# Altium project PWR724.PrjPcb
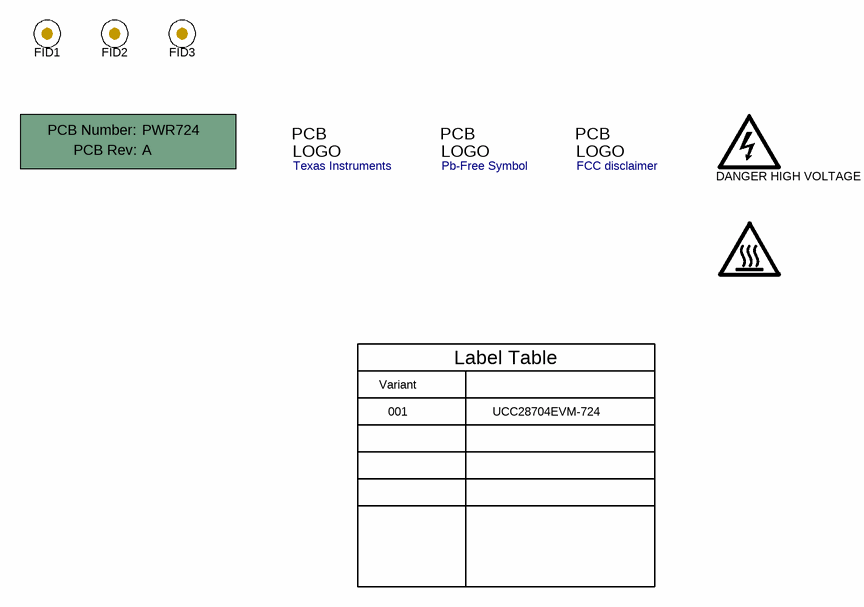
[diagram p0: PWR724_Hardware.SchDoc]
CopyrightYear: 2015; PCB_Layout: M O'Loughlin; PCB_Rev: A; PRJ_Customer: Public Release; PRJ_Engineer: M O'Loughlin; PRJ_Number: PWR724; PRJ_Title: UCC28704EVM-724; SCH_Rev: A; TechSupport: http://www.ti.com/support; TID: N/A
2 sheets, 56 parts. Net scope: global (net labels, ports and power ports of the same name join across sheets).
Board file: PWR724.PcbDoc
Sheets:
  PWR724_Hardware.SchDoc
  PWR724.SchDoc

## Sheet PWR724_Hardware.SchDoc
size 431 x 279 mm; Date: Not shown in title block; ApprovedBy: Not shown in title block; CheckedBy: Not shown in title block; Author: Not shown in title block; CompanyName: Not shown in title block; Engineer: Not shown in title block; Organization: Not shown in title block; Address1: Not shown in title block; Address2: Not shown in title block; Address3: Not shown in title block; Address4: Not shown in title block; DocumentNumber: 1; Revision: Use project parameter SCH_Rev; SheetNumber: 3; SheetTotal: 3; PageSetup: Record=PageOptions¦CenterHorizontal=True¦CenterVertical=True¦PrintScale=1.00¦XCorrection=1.00¦YCorrection=1.00¦PrintKind=0¦BorderSize=5000000¦LeftOffset=0¦BottomOffset=0¦Orientation=2¦PaperLength=1000¦PaperWidth=1000¦Scale=100¦PaperSource=15¦PrintQuality=600¦MediaType=1¦DitherType=10¦PaperKind=Letter¦PrintScaleMode=1

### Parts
!PCB  Printed Circuit Board  (value not drawn)  (mechanical)
FID1  Fiducial  [Fiducial10-20]  (value not drawn)
FID2  Fiducial  [Fiducial10-20]  (value not drawn)
FID3  Fiducial  [Fiducial10-20]  (value not drawn)
Logo1  Texas Instruments  [TI_Stacked_Overlay_Small]  (no BOM)
Logo2  Pb-Free Symbol  [Pb-Free_Overlay_Small]  (no BOM)
Logo3  FCC disclaimer  [FCC_disclaimer]  (no BOM)
LOGO4  DANGER HIGH VOLTAGE  [IEC_HighVoltage_Small]  (no BOM)
LOGO5  CAUTION HOT SURFACE  [IEC_HotSurface_Small]  (value not drawn)  (no BOM)

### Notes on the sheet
- Variant
- Label Table
- 001
- UCC28704EVM-724

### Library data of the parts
!PCB = PCB: Manufacturer: Any; PartNumber: PWR724; SymbolCreator: a0412235
FID1-FID3 = Fiducial: Fiducial mark.  There is nothing to buy or mount.; SymbolCreator: codlsc
Logo1 = TI_Logo: Texas Instrument Corporate Signature; SymbolCreator: a0412235
Logo2 = Pb-Free: SymbolCreator: a0412235
Logo3 = FCC_disclaimer: SymbolCreator: codlsc
LOGO4 = IEC_HighVoltage: IEC 61010-1 High Voltage Warning; SymbolCreator: a0412235
LOGO5 = IEC_HotSurface: IEC 61010-1 Hot Surface Warning; SymbolCreator: a0412235

## Sheet PWR724.SchDoc
size 431 x 279 mm; Date: Not shown in title block; ApprovedBy: Not shown in title block; CheckedBy: Not shown in title block; Author: Not shown in title block; CompanyName: Not shown in title block; Engineer: Not shown in title block; Organization: Not shown in title block; Address1: Not shown in title block; Address2: Not shown in title block; Address3: Not shown in title block; Address4: Not shown in title block; DocumentNumber: 1; Revision: Use project parameter SCH_Rev; SheetNumber: 1; SheetTotal: 3; PageSetup: Record=PageOptions¦CenterHorizontal=True¦CenterVertical=True¦PrintScale=1.00¦XCorrection=1.00¦YCorrection=1.00¦PrintKind=0¦BorderSize=5000000¦LeftOffset=0¦BottomOffset=0¦Orientation=2¦PaperLength=1000¦PaperWidth=1000¦Scale=100¦PaperSource=15¦PrintQuality=600¦MediaType=1¦DitherType=10¦PaperKind=Letter¦PrintScaleMode=1
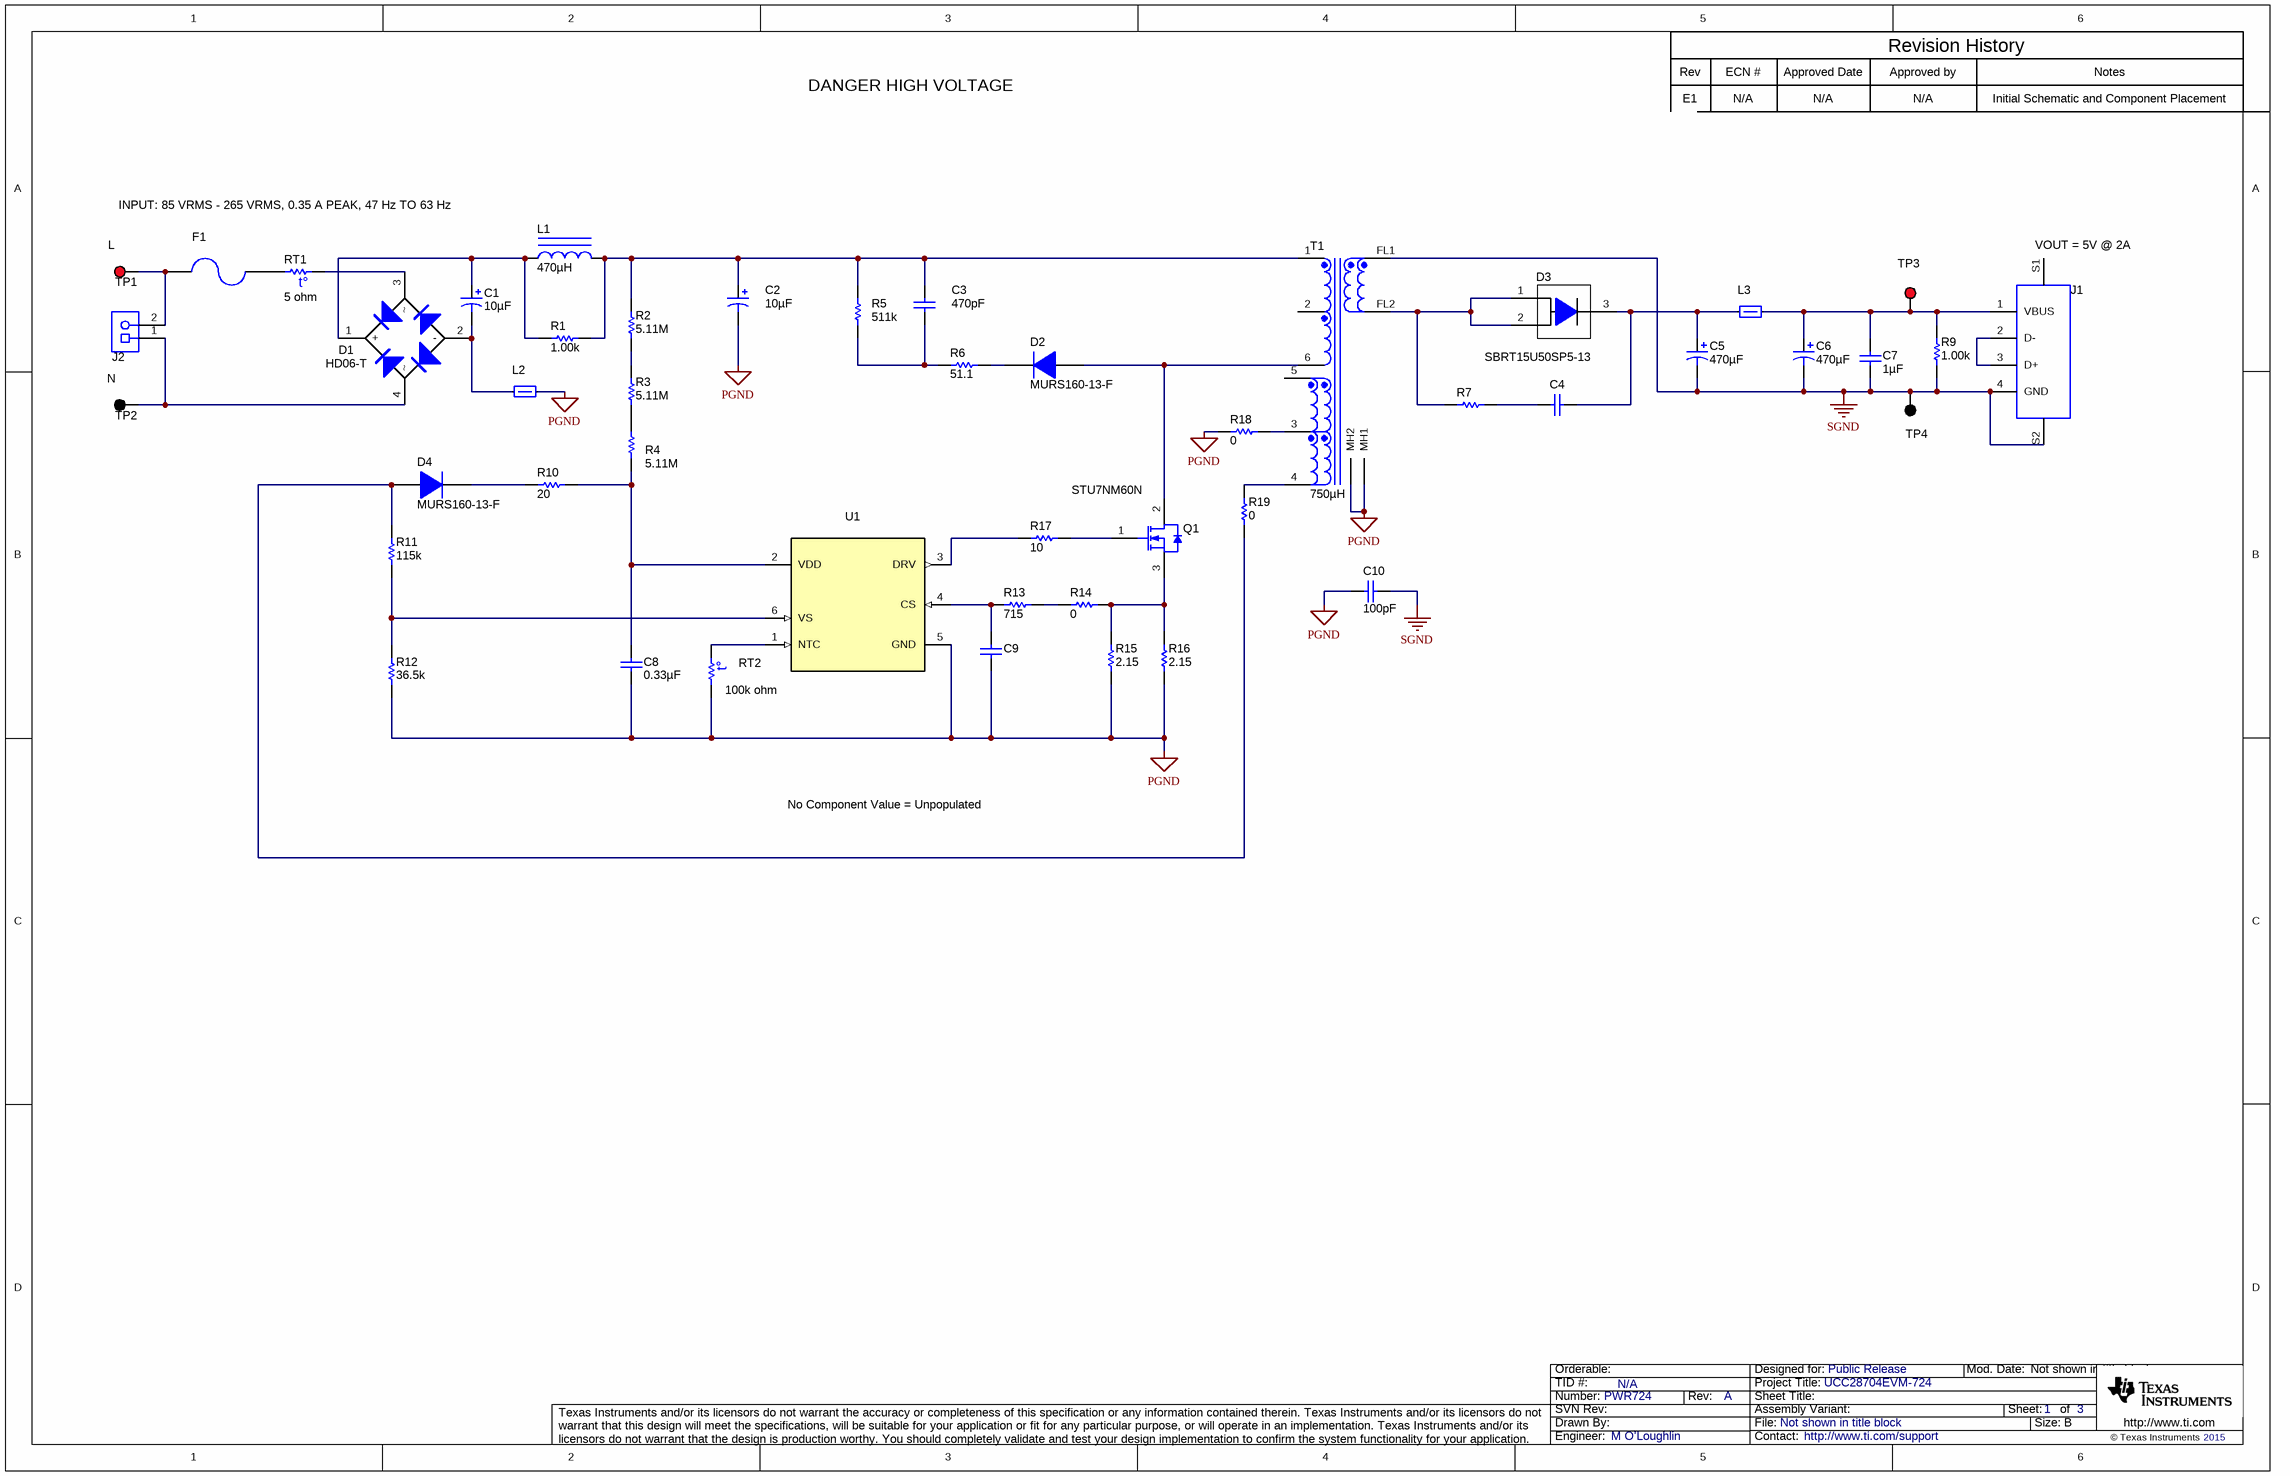
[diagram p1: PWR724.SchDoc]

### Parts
C1  ValueDisplayed: 10µF  [CAPPRD500W60D1000H2000_Horizontal_DOWN]  (hidden comment: UCS2G100MPD1TD)
C2  ValueDisplayed: 10µF  [CAPPRD500W60D1000H2000_Horizontal_UP]  (hidden comment: UCS2G100MPD1TD)
C3  ValueDisplayed: 470pF  [1206]  (hidden comment: GRM31A7U2J471JW31D)
C4  08055A101JAT2A  [0805_HV]  (value not drawn)
C5  ValueDisplayed: 470µF  [LF_1000x1300]  (hidden comment: PLF1C471MDO1)
C6  ValueDisplayed: 470µF  [LF_1000x1300]  (hidden comment: PLF1C471MDO1)
C7  ValueDisplayed: 1µF  [0603]  (hidden comment: C1608X7R1E105K080AB)
C8  ValueDisplayed: 0.33µF  [1206]  (hidden comment: GRM319R71H334KA01D)
C9  06035A270JAT2A  [0603]  (value not drawn)
C10  ValueDisplayed: 100pF  [CD_700x1100x700]  (hidden comment: CD70-B2GA101KYNKA)
D1  HD06-T  [MiniDIP]
D2  MURS160-13-F  [SMB]
D3  SBRT15U50SP5-13  [PowerDI5]
D4  MURS160-13-F  [SMB]
F1  RST 500  [Fuse_RST]  (value not drawn)
J1  923  [Keystone_923]  (value not drawn)
J2  1715721  [PhoenixContact_1715721]  (value not drawn)
L1  ValueDisplayed: 470µH  [RLB0914]  (hidden comment: RLB0914-471KL)
L2  742792121  [1206_190]  (value not drawn)
L3  742792121  [1206_190]  (value not drawn)
Q1  STU7NM60N  [IPAK]
R1  ValueDisplayed: 1.00k  [1206]  (hidden comment: CRCW12061K00FKEA)
R2  ValueDisplayed: 5.11M  [0805_HV]  (hidden comment: CRCW08055M11FKEA)
R3  ValueDisplayed: 5.11M  [0805_HV]  (hidden comment: CRCW08055M11FKEA)
R4  ValueDisplayed: 5.11M  [0805_HV]  (hidden comment: CRCW08055M11FKEA)
R5  ValueDisplayed: 511k  [1206]  (hidden comment: CRCW1206511KFKEA)
R6  ValueDisplayed: 51.1  [0805_HV]  (hidden comment: CRCW080551R1FKEA)
R7  CRCW0805510KJNEA  [0805_HV]  (value not drawn)
R9  ValueDisplayed: 1.00k  [0603]  (hidden comment: CRCW06031K00FKEA)
R10  ValueDisplayed: 20  [0805_HV]  (hidden comment: CRCW080520R0JNEA)
R11  ValueDisplayed: 115k  [0805_HV]  (hidden comment: CRCW0805115KFKEA)
R12  ValueDisplayed: 36.5k  [0603]  (hidden comment: CRCW060336K5FKEA)
R13  ValueDisplayed: 715  [0603]  (hidden comment: RC0603FR-07715RL)
R14  ValueDisplayed: 0  [1206]  (hidden comment: MCR18EZHJ000)
R15  ValueDisplayed: 2.15  [0805_HV]  (hidden comment: CRCW08052R15FKEA)
R16  ValueDisplayed: 2.15  [0805_HV]  (hidden comment: CRCW08052R15FKEA)
R17  ValueDisplayed: 10  [0603]  (hidden comment: CRCW060310R0JNEAHP)
R18  ValueDisplayed: 0  [1206]  (hidden comment: MCR18EZHJ000)
R19  ValueDisplayed: 0  [1206]  (hidden comment: MCR18EZHJ000)
RT1  value 5 ohm  [MF72D5]  (hidden comment: MF72-005D5)
RT2  value 100k ohm  [0603]  (hidden comment: NTCG164KF104F)
T1  ValueDisplayed: 750µH  [Wurth_750315841]  (hidden comment: 750315841)
TP1  5010  [Keystone5010]  (value not drawn)
TP2  5011  [Keystone5011]  (value not drawn)
TP3  5010  [Keystone5010]  (value not drawn)
TP4  5011  [Keystone5011]  (value not drawn)
U1  UCC28704DBVR-1  [DBV0006A_N]  (value not drawn)

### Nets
PGND: C2.2(-) C8.2 C9.2 C10.2 L2.2 R12.1 R15.1 R16.1 R18.1 RT2.1 T1.MH1 T1.MH2 U1.5(GND)
SGND: C5.2(-) C6.2(-) C7.2 C10.1 J1.4(GND) J1.S2 R9.1 T1.FL1 TP4.1
NetC1_1: C1.1(+) D1.1(+) L1.1 R1.2
NetC1_2: C1.2(-) D1.2(-) L2.1
NetC2_1: C2.1(+) C3.1 L1.2 R1.1 R2.2 R5.2 T1.1
NetC3_2: C3.2 R5.1 R6.1
NetC4_1: C4.1 C5.1(+) D3.3(K) L3.1
NetC4_2: C4.2 R7.2
NetC6_1: C6.1(+) C7.1 J1.1(VBUS) L3.2 R9.2 TP3.1
NetC8_1: C8.1 R4.1 R10.1 U1.2(VDD)
NetC9_1: C9.1 R13.1 U1.4(CS)
NetD1_3: D1.3 RT1.2
NetD1_4: D1.4 J2.1 TP2.1
NetD2_1: D2.1(K) R6.2
NetD2_2: D2.2(A) Q1.2(D) T1.6
NetD3_1: D3.1(A) D3.2(A) R7.1 T1.FL2
NetD4_1: D4.1(K) R10.2
NetD4_2: D4.2(A) R11.2 R19.1
NetF1_1: F1.1 RT1.1
NetF1_2: F1.2 J2.2 TP1.1
NetJ1_2: J1.2(D-) J1.3(D+)
NetQ1_1: Q1.1(G) R17.2
NetQ1_3: Q1.3(S) R14.2 R15.2 R16.2
NetR2_1: R2.1 R3.2
NetR3_1: R3.1 R4.2
NetR11_1: R11.1 R12.2 U1.6(VS)
NetR13_2: R13.2 R14.1
NetR17_1: R17.1 U1.3(DRV)
NetR18_2: R18.2 T1.3
NetR19_2: R19.2 T1.4
NetRT2_2: RT2.2 U1.1(NTC)

Not connected (* = marked no-connect by the designer): J1 S1; T1 2 5

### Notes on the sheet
- DANGER HIGH VOLTAGE
- Rev
- E1
- ECN #
- N/A
- Approved Date
- Approved by
- Revision History
- Notes
- Initial Schematic and Component Placement
- INPUT: 85 VRMS - 265 VRMS, 0.35 A PEAK, 47 Hz TO 63 Hz
- (near TP1) L
- (near J1) VOUT = 5V @ 2A
- (near TP2) N
- No Component Value = Unpopulated

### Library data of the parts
C1 C2 = UCS2G100MPD1TD: CAP, AL, 10 µF, 400 V, +/- 20%, TH; Manufacturer: Nichicon; Polarized: Y; CompType: Capacitor; Value: 10uF; U/M: EA; Cap_F: 0.00001; Tolerance_%: 20; Value1: Unknown; VDC_V: 400; Value2: 400V; IRMS_A: 0.35; TaMin_C: -40; TaMax_C: 105; Cap_Case: CAPPRD500W60D1000H2000; AEC Category: Q200; AEC Qualified: N
C3 = GRM31A7U2J471JW31D: CAP, CERM, 470 pF, 630 V, +/- 5%, U2J, 1206; Manufacturer: MuRata; Polarized: N; CompType: Capacitor; Value: 470pF; U/M: EA; Cap_F: 0.00000000047; Tolerance_%: 5; Value1: Unknown; VDC_V: 630; Value2: 630V; TaMin_C: -55; TaMax_C: 125; AEC Category: Q200
C4 = 08055A101JAT2A: CAP, CERM, 100 pF, 50 V, +/- 5%, C0G/NP0, 0805; Manufacturer: AVX; Polarized: N; CompType: Capacitor; Value: 100pF; U/M: EA; Cap_F: 0.0000000001; Tolerance_%: 5; ESR_ohm: 0.356; Value1: 0.356 ohm; VDC_V: 50; Value2: 50V; TaMin_C: -55; TaMax_C: 125; Cap_Case: 0805; AEC Category: Q200
C5 C6 = PLF1C471MDO1: CAP, AL, 470 µF, 16 V, +/- 20%, 0.009 ohm, TH; Manufacturer: Nichicon; Polarized: Y; CompType: Capacitor; Value: 470uF; U/M: EA; Cap_F: 0.00047; Tolerance_%: 20; VDC_V: 16; Value2: 16V; ESR_ohm: 0.009; IRMS_A: 6.1; TaMin_C: -55; TaMax_C: 105; Cap_Case: 10x13mm; AEC Category: Q200
C7 = C1608X7R1E105K080AB: CAP, CERM, 1 µF, 25 V, +/- 10%, X7R, 0603; Manufacturer: TDK; Polarized: N; CompType: Capacitor; Value: 1uF; U/M: EA; Cap_F: 0.000001; Tolerance_%: 10; Value1: Unknown; VDC_V: 25; Value2: 25V; TaMin_C: -55; TaMax_C: 125; AEC Category: Q200
C8 = GRM319R71H334KA01D: CAP, CERM, 0.33 µF, 50 V, +/- 10%, X7R, 1206; Manufacturer: MuRata; Polarized: N; CompType: Capacitor; Value: 0.33uF; U/M: EA; Cap_F: 0.00000033; Tolerance_%: 10; Value1: Unknown; VDC_V: 50; Value2: 50V; TaMin_C: -55; TaMax_C: 125; AEC Category: Q200
C9 = 06035A270JAT2A: CAP, CERM, 27 pF, 50 V, +/- 5%, C0G/NP0, 0603; Manufacturer: AVX; Polarized: N; CompType: Capacitor; Value: 27pF; U/M: EA; Cap_F: 0.000000000027; Tolerance_%: 5; ESR_ohm: 0.232; Value1: 0.232 ohm; VDC_V: 50; Value2: 50V; TaMin_C: -55; TaMax_C: 125; AEC Category: Q200
C10 = CD70-B2GA101KYNKA: CAP, CERM, 100 pF, 440 V, +/- 10%, B, 7.0x11.0x7.0mm; Manufacturer: TDK; Polarized: N; CompType: Capacitor; Value: 100pF; U/M: EA; VDC_V: 440; Tolerance_%: 10; Cap_F: 0.0000000001; Value1: Unknown; Value2: 440V; TaMin_C: -25; TaMax_C: 105; Cap_Case: 7x7x11mm; AEC Category: Q200
D1 = HD06-T: Diode, Switching-Bridge, 600 V, 0.8 A, MiniDIP; Manufacturer: Diodes Inc.; Value: 600V; U/M: EA; Vf_V: 1; Io_A: 0.8; Value1: 0.8A; Vr_V: 600; Value2: 1V; TJmax_C: 150; AEC Category: Q101
D2 D4 = MURS160-13-F: Diode, Ultrafast, 600 V, 1 A, SMB; Manufacturer: Diodes Inc.; U/M: EA; Vf_V: 1.25; Value: 600V; Value1: 1A; Value2: 1.25V; Io_A: 1; Vr_V: 600; TJmax_C: 150; RJC_CperW: 13; AEC Category: Q101
D3 = SBRT15U50SP5-13: Diode, Super Barrier Rectifier, 50 V, 15 A, AEC-Q101, PowerDI5; Manufacturer: Diodes Inc.; SymbolCreator: a0412235; U/M: EA; Vf_V: 0.47; Value: 50V; Value1: 15A; Value2: 0.47V; Io_A: 15; Vr_V: 50; TJmax_C: 150; AEC Category: Q101; AEC Qualified: Y
F1 = RST 500: Fuse, 0.5 A, 250VAC/VDC, TH; Manufacturer: Bel Fuse; VDC_V: 250; Irating_A: 0.5; Rtyp_Ohm: 0.18; MeltingTyp: 1.7
J1 = 923: Connector, Receptacle, USB Type A, Vertical, TH; Manufacturer: Keystone; SymbolCreator: Altium; U/M: EA
J2 = 1715721: Terminal Block, 5.08 mm, 2x1, TH; Manufacturer: Phoenix Contact; SymbolCreator: a0412235; Pitch_mm: 5.08; Gender: Female; Row_Count: 1; ContactFinish: Tin; Current_A: 17.5; Voltage_V: 400; Cert_CSA: Y; Cert_CULUS: N
L1 = RLB0914-471KL: Inductor, Wirewound, Ferrite, 470 µH, 0.5 A, 1.3 ohm, TH; Manufacturer: Bourns; Value: 470uH; Ind_H: 470.0E-6; Imax_A: 0.5; Irms: 0.5A @ C rise; DCR_ohm: 1.3; Value1: 1.3 ohm; Value2: 0.5A; AEC Category: Q200; AEC Qualified: N
L2 L3 = 742792121: Ferrite Bead, 300 ohm @ 100 MHz, 3 A, 1206_190; Manufacturer: Wurth Elektronik; Value: 300 ohm; Imax_A: 3; DCR_ohm: 0.06; Value1: 0.06 ohm; Value2: 3A; ZTyp@100MHz_Ohm: 300
Q1 = STU7NM60N: MOSFET, N-CH, 600 V, 5 A, IPAK; Manufacturer: STMicroelectronics; Alternate Manufacturer: None; Value: 600V; VdsMax_V: 600; IdsMax_A: 5; U/M: EA; ChType: N; Value1: ? ohm; Value2: 14 nC; QgTyp_nC: 14; Vgs_V: 25; AEC Category: Q101
R1 = CRCW12061K00FKEA: RES, 1.00 k, 1%, 0.25 W, 1206; Manufacturer: Vishay-Dale; CompType: Resistor; Value: 1.00k; Res_ohm: 1000; Value_Code: 1k00; Tolerance_%: 1; Power_W: 0.25; Value2: 0.25W; VDC_V: 200; TempCo: 100 ppm/C; EIA_Code: E96; U/M: EA; AEC Category: Q200
R2-R4 = CRCW08055M11FKEA: RES, 5.11 M, 1%, 0.125 W, 0805; Manufacturer: Vishay-Dale; CompType: Resistor; Value: 5.11Meg; Res_ohm: 5110000; Value_Code: 5M11; Tolerance_%: 1; Power_W: 0.125; Value2: 0.125W; VDC_V: 150; TempCo: 100 ppm/C; EIA_Code: E96; U/M: EA; AEC Category: Q200
R5 = CRCW1206511KFKEA: RES, 511 k, 1%, 0.25 W, 1206; Manufacturer: Vishay-Dale; CompType: Resistor; Value: 511k; Res_ohm: 511000; Tolerance_%: 1; Power_W: 0.25; Value2: 0.25W; VDC_V: 200; TempCo: 100 ppm/C; EIA_Code: E96; U/M: EA; AEC Category: Q200
R6 = CRCW080551R1FKEA: RES, 51.1, 1%, 0.125 W, 0805; Manufacturer: Vishay-Dale; CompType: Resistor; Value: 51.1; Value_Code: 51R1; Tolerance_%: 1; Power_W: 0.125; Value2: 0.125W; VDC_V: 150; TempCo: 100 ppm/C; EIA_Code: E96; U/M: EA; AEC Category: Q200
R7 = CRCW0805510KJNEA: RES, 510 k, 5%, 0.125 W, 0805; Manufacturer: Vishay-Dale; CompType: Resistor; Value: 510k; Res_ohm: 510000; Tolerance_%: 5; Power_W: 0.125; Value2: 0.125W; VDC_V: 150; TempCo: 200 ppm/C; EIA_Code: E24; U/M: EA; AEC Category: Q200
R9 = CRCW06031K00FKEA: RES, 1.00 k, 1%, 0.1 W, 0603; Manufacturer: Vishay-Dale; CompType: Resistor; Value: 1.00k; Res_ohm: 1000; Value_Code: 1k00; Tolerance_%: 1; Power_W: 0.1; Value2: 0.1W; VDC_V: 75; TempCo: 100 ppm/C; EIA_Code: E96; U/M: EA; AEC Category: Q200
R10 = CRCW080520R0JNEA: RES, 20, 5%, 0.125 W, 0805; Manufacturer: Vishay-Dale; CompType: Resistor; Value: 20; Value_Code: 20R0; Tolerance_%: 5; Power_W: 0.125; Value2: 0.125W; VDC_V: 150; TempCo: 200 ppm/C; EIA_Code: E24; U/M: EA; AEC Category: Q200
R11 = CRCW0805115KFKEA: RES, 115 k, 1%, 0.125 W, 0805; Manufacturer: Vishay-Dale; CompType: Resistor; Value: 115k; Res_ohm: 115000; Tolerance_%: 1; Power_W: 0.125; Value2: 0.125W; VDC_V: 150; TempCo: 100 ppm/C; EIA_Code: E96; U/M: EA; AEC Category: Q200
R12 = CRCW060336K5FKEA: RES, 36.5 k, 1%, 0.1 W, 0603; Manufacturer: Vishay-Dale; CompType: Resistor; Value: 36.5k; Res_ohm: 36500; Value_Code: 36k5; Tolerance_%: 1; Power_W: 0.1; Value2: 0.1W; VDC_V: 75; TempCo: 100 ppm/C; EIA_Code: E96; U/M: EA; AEC Category: Q200
R13 = RC0603FR-07715RL: RES, 715, 1%, 0.1 W, 0603; Manufacturer: Yageo America; CompType: Resistor; Value: 715; Value_Code: 715R; Tolerance_%: 1; Power_W: 0.1; Value2: 0.1W; VDC_V: 150; TempCo: 200 ppm/C; EIA_Code: E96; U/M: EA; AEC Category: Q200
R14 R18 R19 = MCR18EZHJ000: RES, 0, 5%, 0.25 W, 1206; Manufacturer: Rohm; CompType: Resistor; Value: 0; Value_Code: 0000; Tolerance_%: 5; Power_W: 0.25; Value2: 0.25W; VDC_V: 200; TempCo: 200 ppm/C; EIA_Code: E24; U/M: EA; AEC Category: Q200
R15 R16 = CRCW08052R15FKEA: RES, 2.15, 1%, 0.125 W, 0805; Manufacturer: Vishay-Dale; CompType: Resistor; Value: 2.15; Value_Code: 2R15; Tolerance_%: 1; Power_W: 0.125; Value2: 0.125W; VDC_V: 150; TempCo: 100 ppm/C; EIA_Code: E96; U/M: EA; AEC Category: Q200
R17 = CRCW060310R0JNEAHP: RES, 10, 5%, 0.25 W, 0603; Manufacturer: Vishay-Dale; CompType: Resistor; Value: 10; Value_Code: 10R0; Tolerance_%: 5; Power_W: 0.25; Value2: 0.25W; VDC_V: 75; TempCo: 200 ppm/C; EIA_Code: E24; U/M: EA; AEC Category: Q200
RT1 = MF72-005D5: Thermistor NTC, 5 ohm, 20%, MF72D5 TH; Manufacturer: Cantherm; Tolerance_%: 20; TaMin_C: -55; TaMax_C: 200; U/M: EA
RT2 = NTCG164KF104F: Thermistor NTC, 100k ohm, 1%, 0603; Manufacturer: TDK; Tolerance_%: 1; TaMin_C: -40; TaMax_C: 125; U/M: EA
T1 = 750315841: Transformer, 750 uH, TH; Manufacturer: Wurth Elektronik; SymbolCreator: Altium; Value: 750uH; Lp: 750; DCR_ohm: 0.56; LeakageL: 4
TP1 TP3 = 5010: Test Point, Multipurpose, Red, TH; Manufacturer: Keystone; CompType: Test Point Loop; U/M: EA
TP2 TP4 = 5011: Test Point, Multipurpose, Black, TH; Manufacturer: Keystone; CompType: Test Point Loop; U/M: EA
U1 = UCC28704DBVR-1: CV/CC Flyback Controller with Primary-Side Regulation (PSR) and CC Under-Voltage Protection, DBV0006A; Alternate PartNumber: UCC28704DBVT-1; Manufacturer: Texas Instruments; SymbolCreator: a0411947; CompType: IC; U/M: EA

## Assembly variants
001: not fitted C4 C9 FID1 FID2 FID3 R7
